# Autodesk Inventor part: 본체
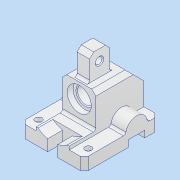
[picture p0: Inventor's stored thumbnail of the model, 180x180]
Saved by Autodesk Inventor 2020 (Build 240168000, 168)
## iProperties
Created: 2022-08
Part Number: 본체
Material: 알루미늄 6061
Document SubType Name: Modeling
Designer: user
Density: 2.7 g/cm^3
Appearance: 알루미늄 - 평지
Mass: 499.24 g
Surface Area: 337.473 cm^2
Volume: 184.904 cm^3
Author: user
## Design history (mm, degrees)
sketch "스케치1"
  geometry: L1 (-20, 18)-(20, 18); L2 (20, 18)-(20, -42); L3 (20, -42)-(-20, -42); L4 (-20, -42)-(-20, 18); 2 further points
  constraints: 8 end point, 2 parallel, 1 horizontal, 1 midpoint, 1 perpendicular, 1 vertical alignment
  dimensions: "d0" = 42 distance from line of point (0, 0) L3; "d1" = 60 distance of L3.end L1.start; "d2" = 40 distance of L1.start L1.end
extrude "돌출1" new body sketch "스케치1" distance "d3" = 90; taper "d4" = 0 deg
sketch "스케치2"
  geometry: L1 (-38, -27)-(38, -27); L2 (38, -27)-(38, -42); L3 (38, -42)-(-38, -42); L4 (-38, -42)-(-38, -27); L5 (-20, -42)-(20, -42) reference; 2 further points
  constraints: 8 end point, 2 midpoint, 2 parallel, 1 horizontal, 1 perpendicular
  dimensions: "d5" = 76 distance of L1.start L1.end; "d6" = 15 distance of L3.end L1.start
extrude "돌출2" join sketch "스케치2" distance "d7" = 90; taper "d8" = 0 deg
sketch "스케치3"
  geometry: L1 (-20, 18)-(20, 18); L2 (20, 18)-(20, -23); L3 (20, -23)-(-20, -23); L4 (-20, -23)-(-20, 18); L5 (-38, -42)-(38, -42) reference; 3 further points
  constraints: 8 end point, 2 coincident, 2 parallel, 1 horizontal, 1 perpendicular
  dimensions: "d9" = 19 distance between parallel lines of L5 L3
extrude "돌출3" cut sketch "스케치3" distance "d10" = 32; taper "d11" = 0 deg
sketch "스케치4"
  geometry: L1 (0, 15)-(-90, 15) reference; L2 (-90, 0)-(-90, 15) reference; C1 r 13 at (-63, 15); 1 further point
  constraints: 1 centre point, 1 point on line
  dimensions: "d12" = 26 diameter of C1; "d13" = 27 distance from line of L2 C1.centre
extrude "돌출4" join sketch "스케치4" distance "d14" = 76; taper "d15" = 0 deg
sketch "스케치5"
  geometry: L1 (48, 53)-(18, 53); L2 (18, 53)-(18, 29); L3 (18, 29)-(48, 29); L4 (48, 29)-(48, 53); L5 (18, 0)-(18, 58) reference; L6 (18, 0)-(-27, 0) reference; L7 (-23, 58)-(18, 58) reference; 2 further points
  constraints: 8 end point, 2 parallel, 1 horizontal, 1 midpoint, 1 perpendicular, 1 point on line
  dimensions: "d16" = 24 distance of L3.end L1.start; "d18" = 30 distance of L1.start L1.end; "d27" = 5 distance between parallel lines of L7 L1
extrude "돌출5" join sketch "스케치5" stored distance "d19" = 15; taper "d20" = 0 deg
sketch "스케치6"
  geometry: C1 r 29 at (0, 0); 1 further point
  constraints: 1 centre point, 1 coincident
  dimensions: "d21" = 58 diameter of C1
extrude "돌출6" cut sketch "스케치6" distance "d22" = 18; taper "d23" = 0 deg
sketch "스케치7"
  geometry: L1 (-6, -23)-(6, -23); L2 (6, -23)-(6, -42); L3 (6, -42)-(-6, -42); L4 (-6, -42)-(-6, -23); L5 (-38, -42)-(38, -42) reference; L6 (-17.664, -23)-(17.664, -23) reference; 3 further points
  constraints: 8 end point, 4 midpoint, 2 parallel, 1 horizontal, 1 perpendicular
  dimensions: "d24" = 12 distance of L1.start L1.end
extrude "돌출7" cut sketch "스케치7" distance "d25" = 18; taper "d26" = 0 deg
sketch "스케치8"
  geometry: L1 (-73, 8)-(-53, 8); L2 (-53, 8)-(-53, 0); L3 (-53, 0)-(-73, 0); L4 (-73, 0)-(-73, 8); L5 (0, 0)-(-90, 0) reference; L6 (-90, 0)-(-90, 15) reference; 2 further points
  constraints: 8 end point, 2 parallel, 1 horizontal, 1 midpoint, 1 perpendicular, 1 point on line
  dimensions: "d28" = 20 distance of L1.start L1.end; "d29" = 27 distance from line of L6 point (-63, 0); "d30" = 8 distance of L1.end L2.end
extrude "돌출8" cut sketch "스케치8" extent not by distance; stored distance "d31" = 0; taper "d32" = 0 deg
sketch "스케치9"
  geometry: C1 r 14.5 at (0, 0); 1 further point
  constraints: 1 centre point, 1 coincident
  dimensions: "d33" = 29 diameter of C1
extrude "돌출9" cut sketch "스케치9" distance "d34" = 7; taper "d35" = 0 deg
sketch "스케치10"
  geometry: C1 r 10 at (0, 0); 1 further point
  constraints: 1 centre point, 1 coincident
  dimensions: "d36" = 20 diameter of C1
extrude "돌출10" cut sketch "스케치10" extent not by distance; stored distance "d37" = 0; taper "d38" = 0 deg
sketch "스케치11"
  geometry: L1 (-29, 18)-(-29, 48) reference; C1 r 4 at (-41, 35); 1 further point
  constraints: 1 centre point
  dimensions: "d39" = 8 diameter of C1; "d40" = 35 vertical distance of C1.centre point (0, 0); "d41" = 12 distance from line of C1.centre L1
extrude "돌출11" cut sketch "스케치11" extent not by distance; stored distance "d42" = 0; taper "d43" = 0 deg
sketch "스케치12"
  geometry: L1 (18, 0)-(0, 0) reference; 3 further points
  constraints: 1 horizontal alignment
  dimensions: "d44" = 60 distance of point (68, 13) point (8, 13); "d45" = 30 horizontal distance of point (8, 13) point (38, 90); "d46" = 13 distance from line of L1 point (8, 13)
hole "구멍1" sketch "스케치12" at (8, 13), (68, 13) diameter "d47" = 4.5; stored, may be unused: countersink angle "d51" = 90 deg, drill point angle "d53" = 0 deg; dims "d48" = 16, "d49" = 8, "d50" = 4.4, "d52" = 8
chamfer "모따기1" distance "d54" = 18; stored, may be unused: second distance "d55" = 2, angle "d56" = 45 deg
chamfer "모따기2" distance "d57" = 5; stored, may be unused: second distance "d58" = 2, angle "d59" = 45 deg
chamfer "모따기3" distance "d60" = 1; stored, may be unused: second distance "d61" = 2, angle "d62" = 45 deg
fillet "모깎기1" dims "d63" = 3
node "작업 평면1"
sketch "스케치13"
  geometry: L1 (-72, 45)-(-32, 45) reference; L2 (-32, 7)-(-32, 45) reference; 2 further points
  constraints: 1 other
  dimensions: "d65" = 18 distance from line of L1 point (-58, 27); "d66" = 26 distance from line of L2 point (-58, 27)
feature "엠보싱1" sketch "스케치13" dims "d0" = 42, "d1" = 60, "d2" = 40, "d9" = 19, "d67" = 0.5, "d68" = 0
chamfer "모따기4" distance "d69" = 5; stored, may be unused: second distance "d70" = 2, angle "d71" = 45 deg
node "솔리드1"
feature "A9D066F2-1C7D-4E18-AEED-F7BC21143FA4" dims "d47" = 4.5, "d48" = 16, "d49" = 8, "d50" = 4.4, "d51" = 90 deg, "d52" = 8, "d53" = 0
other parameters: "d64" = 36.25
